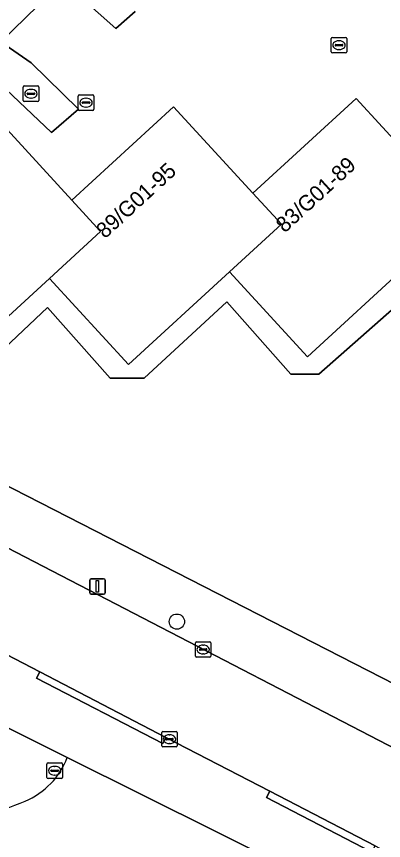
# Model space of a CAD drawing. Extents: x 160349 to 161355, y 381727 to 382854.
# Drawn here: x 160831.9 to 160855.5, y 381918.5 to 381971.4 of the extents above; entities that cross this region are included whole.
import ezdxf

# ---------------------------------------------------------------- set-up
doc = ezdxf.new("R2010")
doc.units = 0
for name, color, linetype in [('IMGEO_Boom', 7, 'Continuous'), ('IMGEO_Brandkraan', 7, 'Continuous'), ('IMGEO_Groenvoorziening', 7, 'Continuous'), ('IMGEO_Kolk', 7, 'Continuous'), ('IMGEO_Lichtmast', 7, 'Continuous'), ('IMGEO_Pand', 7, 'Continuous'), ('IMGEO_Pand_nummerreeks', 7, 'Continuous'), ('IMGEO_Rijbaan_lokaal_gesloten', 7, 'Continuous'), ('IMGEO_Rijbaan_lokaal_open', 7, 'Continuous'), ('IMGEO_Voetpad_halfverhard', 7, 'Continuous'), ('IMGEO_Voetpad_open', 7, 'Continuous')]:
    doc.layers.add(name, color=color, linetype=linetype)

msp = doc.modelspace()

# ---------------------------------------------------------------- linework, layer by layer
at = {"layer": 'IMGEO_Boom'}
msp.add_circle((160842.225, 381932.523), 0.489, dxfattribs=at)
at = {"layer": 'IMGEO_Brandkraan'}
for p, q in [((160832.359, 381965.97), (160832.359, 381966.822)), ((160832.434, 381966.896), (160833.286, 381966.896)), ((160832.618, 381966.39), (160832.618, 381966.402)), ((160832.661, 381966.439), (160833.059, 381966.439)), ((160832.847, 381966.676), (160832.872, 381966.676)), ((160833.102, 381966.402), (160833.102, 381966.39)), ((160833.36, 381966.822), (160833.36, 381965.97)), ((160833.286, 381965.896), (160832.434, 381965.896)), ((160833.056, 381966.353), (160832.658, 381966.353)), ((160832.87, 381966.116), (160832.845, 381966.116))]:
    msp.add_line(p, q, dxfattribs=at)
for points in [[(160832.359, 381965.97), (160832.359, 381966.822)], [(160832.434, 381966.896), (160833.286, 381966.896)], [(160833.36, 381966.822), (160833.36, 381965.97)], [(160833.286, 381965.896), (160832.434, 381965.896)]]:
    msp.add_lwpolyline(points, dxfattribs=at)
for centre, radius, start, end in [((160832.436, 381966.82), 0.0765, 91.552, 178.448), ((160832.436, 381966.82), 0.0765, 91.552, 178.448), ((160832.658, 381966.399), 0.0403, 85.8775, 175.7526), ((160832.655, 381966.389), 0.0366, 178.938, 274.7102), ((160833.059, 381966.396), 0.043, 264.8664, 352.4533), ((160833.063, 381966.401), 0.0386, 1.7309, 96.639), ((160833.284, 381966.82), 0.0765, 1.552, 88.448), ((160833.284, 381966.82), 0.0765, 1.552, 88.448), ((160832.436, 381965.972), 0.0765, 181.552, 268.448), ((160832.436, 381965.972), 0.0765, 181.552, 268.448), ((160833.284, 381965.972), 0.0765, 271.552, 358.448), ((160833.284, 381965.972), 0.0765, 271.552, 358.448)]:
    msp.add_arc(centre, radius, start, end, dxfattribs=at)
for centre, major_axis, ratio, start_param, end_param in [((160832.846, 381966.396), (-0.387, 0.002), 0.722429, 4.712389, 7.853982), ((160832.871, 381966.396), (-0.39, 0.002), 0.717154, 1.570796, 4.712389)]:
    msp.add_ellipse(centre, major_axis=major_axis, ratio=ratio, start_param=start_param, end_param=end_param, dxfattribs=at)
at = {"layer": 'IMGEO_Groenvoorziening'}
for points in [[(160846.705, 382000), (160826.232, 381970.197), (160830.848, 381967.059), (160834.186, 381963.909), (160835.921, 381965.403), (160832.878, 381968.382), (160830.935, 381969.72), (160834.915, 381973.622), (160838.299, 381970.579), (160839.544, 381971.672)], [(160857.092, 381953.481), (160851.346, 381948.396), (160849.539, 381948.396), (160845.436, 381953.033), (160840.118, 381948.151), (160837.948, 381948.151), (160833.93, 381952.676), (160828.424, 381947.509), (160826.348, 381947.553), (160820.135, 381954.319), (160820.858, 381954.984), (160824.089, 381957.951), (160823.753, 381958.316), (160823.374, 381957.967), (160823.024, 381958.349), (160823.707, 381958.976), (160820.18, 381961.222), (160815.016, 381954.084)], [(160815.913, 381949.125), (160859.732, 381926.696)]]:
    msp.add_lwpolyline(points, dxfattribs=at)
at = {"layer": 'IMGEO_Kolk'}
for p, q in [((160852.129, 381969.086), (160852.129, 381969.938)), ((160852.204, 381970.012), (160853.056, 381970.012)), ((160852.617, 381969.792), (160852.642, 381969.792)), ((160853.13, 381969.938), (160853.13, 381969.086)), ((160852.388, 381969.506), (160852.388, 381969.518)), ((160852.826, 381969.469), (160852.428, 381969.469)), ((160852.431, 381969.555), (160852.829, 381969.555)), ((160852.64, 381969.232), (160852.615, 381969.232)), ((160852.872, 381969.518), (160852.872, 381969.506)), ((160853.056, 381969.012), (160852.204, 381969.012)), ((160835.895, 381965.398), (160835.895, 381966.25)), ((160835.97, 381966.324), (160836.822, 381966.324)), ((160836.197, 381965.867), (160836.595, 381965.867)), ((160836.383, 381966.104), (160836.408, 381966.104)), ((160836.896, 381966.25), (160836.896, 381965.398)), ((160836.154, 381965.818), (160836.154, 381965.83)), ((160836.592, 381965.781), (160836.194, 381965.781)), ((160836.406, 381965.544), (160836.381, 381965.544)), ((160836.638, 381965.83), (160836.638, 381965.818)), ((160836.822, 381965.324), (160835.97, 381965.324)), ((160843.413, 381930.308), (160843.413, 381931.16)), ((160843.488, 381931.234), (160844.34, 381931.234)), ((160843.901, 381931.014), (160843.926, 381931.014)), ((160844.414, 381931.16), (160844.414, 381930.308)), ((160843.672, 381930.728), (160843.672, 381930.74)), ((160844.11, 381930.691), (160843.712, 381930.691)), ((160843.715, 381930.777), (160844.113, 381930.777)), ((160843.924, 381930.454), (160843.899, 381930.454)), ((160844.156, 381930.74), (160844.156, 381930.728)), ((160844.34, 381930.234), (160843.488, 381930.234)), ((160841.251, 381924.555), (160841.251, 381925.407)), ((160841.326, 381925.481), (160842.178, 381925.481)), ((160841.739, 381925.261), (160841.764, 381925.261)), ((160842.252, 381925.407), (160842.252, 381924.555)), ((160841.51, 381924.975), (160841.51, 381924.987)), ((160841.948, 381924.938), (160841.55, 381924.938)), ((160841.553, 381925.024), (160841.951, 381925.024)), ((160841.762, 381924.701), (160841.737, 381924.701)), ((160841.994, 381924.987), (160841.994, 381924.975)), ((160842.178, 381924.481), (160841.326, 381924.481)), ((160833.885, 381922.533), (160833.885, 381923.385)), ((160833.96, 381923.459), (160834.812, 381923.459)), ((160834.373, 381923.239), (160834.398, 381923.239)), ((160834.886, 381923.385), (160834.886, 381922.533)), ((160834.144, 381922.953), (160834.144, 381922.965)), ((160834.582, 381922.916), (160834.184, 381922.916)), ((160834.187, 381923.002), (160834.585, 381923.002)), ((160834.396, 381922.679), (160834.371, 381922.679)), ((160834.628, 381922.965), (160834.628, 381922.953)), ((160834.812, 381922.459), (160833.96, 381922.459))]:
    msp.add_line(p, q, dxfattribs=at)
for points in [[(160852.129, 381969.086), (160852.129, 381969.938)], [(160852.204, 381970.012), (160853.056, 381970.012)], [(160853.13, 381969.938), (160853.13, 381969.086)], [(160853.056, 381969.012), (160852.204, 381969.012)], [(160835.895, 381965.398), (160835.895, 381966.25)], [(160835.97, 381966.324), (160836.822, 381966.324)], [(160836.896, 381966.25), (160836.896, 381965.398)], [(160836.822, 381965.324), (160835.97, 381965.324)], [(160843.413, 381930.308), (160843.413, 381931.16)], [(160843.488, 381931.234), (160844.34, 381931.234)], [(160844.414, 381931.16), (160844.414, 381930.308)], [(160844.34, 381930.234), (160843.488, 381930.234)], [(160841.251, 381924.555), (160841.251, 381925.407)], [(160841.326, 381925.481), (160842.178, 381925.481)], [(160842.252, 381925.407), (160842.252, 381924.555)], [(160842.178, 381924.481), (160841.326, 381924.481)], [(160833.885, 381922.533), (160833.885, 381923.385)], [(160833.96, 381923.459), (160834.812, 381923.459)], [(160834.886, 381923.385), (160834.886, 381922.533)], [(160834.812, 381922.459), (160833.96, 381922.459)]]:
    msp.add_lwpolyline(points, dxfattribs=at)
for centre, radius, start, end in [((160852.206, 381969.936), 0.0765, 91.552, 178.448), ((160852.206, 381969.936), 0.0765, 91.552, 178.448), ((160853.054, 381969.936), 0.0765, 1.552, 88.448), ((160853.054, 381969.936), 0.0765, 1.552, 88.448), ((160852.206, 381969.088), 0.0765, 181.552, 268.448), ((160852.206, 381969.088), 0.0765, 181.552, 268.448), ((160852.428, 381969.515), 0.0403, 85.8775, 175.7526), ((160852.425, 381969.505), 0.0366, 178.938, 274.7102), ((160852.829, 381969.512), 0.043, 264.8664, 352.4533), ((160852.833, 381969.517), 0.0386, 1.7309, 96.639), ((160853.054, 381969.088), 0.0765, 271.552, 358.448), ((160853.054, 381969.088), 0.0765, 271.552, 358.448), ((160835.972, 381966.248), 0.0765, 91.552, 178.448), ((160835.972, 381966.248), 0.0765, 91.552, 178.448), ((160836.194, 381965.827), 0.0403, 85.8775, 175.7526), ((160836.599, 381965.829), 0.0386, 1.7309, 96.639), ((160836.82, 381966.248), 0.0765, 1.552, 88.448), ((160836.82, 381966.248), 0.0765, 1.552, 88.448), ((160835.972, 381965.4), 0.0765, 181.552, 268.448), ((160835.972, 381965.4), 0.0765, 181.552, 268.448), ((160836.191, 381965.817), 0.0366, 178.938, 274.7102), ((160836.595, 381965.824), 0.043, 264.8664, 352.4533), ((160836.82, 381965.4), 0.0765, 271.552, 358.448), ((160836.82, 381965.4), 0.0765, 271.552, 358.448), ((160843.49, 381931.158), 0.0765, 91.552, 178.448), ((160843.49, 381931.158), 0.0765, 91.552, 178.448), ((160844.338, 381931.158), 0.0765, 1.552, 88.448), ((160844.338, 381931.158), 0.0765, 1.552, 88.448), ((160843.712, 381930.737), 0.0403, 85.8775, 175.7526), ((160843.709, 381930.727), 0.0366, 178.938, 274.7102), ((160844.113, 381930.734), 0.043, 264.8664, 352.4533), ((160844.117, 381930.739), 0.0386, 1.7309, 96.639), ((160843.49, 381930.31), 0.0765, 181.552, 268.448), ((160843.49, 381930.31), 0.0765, 181.552, 268.448), ((160844.338, 381930.31), 0.0765, 271.552, 358.448), ((160844.338, 381930.31), 0.0765, 271.552, 358.448), ((160841.328, 381925.405), 0.0765, 91.552, 178.448), ((160841.328, 381925.405), 0.0765, 91.552, 178.448), ((160842.176, 381925.405), 0.0765, 1.552, 88.448), ((160842.176, 381925.405), 0.0765, 1.552, 88.448), ((160841.55, 381924.984), 0.0403, 85.8775, 175.7526), ((160841.547, 381924.974), 0.0366, 178.938, 274.7102), ((160841.951, 381924.981), 0.043, 264.8664, 352.4533), ((160841.955, 381924.986), 0.0386, 1.7309, 96.639), ((160841.328, 381924.557), 0.0765, 181.552, 268.448), ((160841.328, 381924.557), 0.0765, 181.552, 268.448), ((160842.176, 381924.557), 0.0765, 271.552, 358.448), ((160842.176, 381924.557), 0.0765, 271.552, 358.448), ((160833.962, 381923.383), 0.0765, 91.552, 178.448), ((160833.962, 381923.383), 0.0765, 91.552, 178.448), ((160834.81, 381923.383), 0.0765, 1.552, 88.448), ((160834.81, 381923.383), 0.0765, 1.552, 88.448), ((160833.962, 381922.535), 0.0765, 181.552, 268.448), ((160833.962, 381922.535), 0.0765, 181.552, 268.448), ((160834.184, 381922.962), 0.0403, 85.8775, 175.7526), ((160834.181, 381922.952), 0.0366, 178.938, 274.7102), ((160834.585, 381922.959), 0.043, 264.8664, 352.4533), ((160834.589, 381922.964), 0.0386, 1.7309, 96.639), ((160834.81, 381922.535), 0.0765, 271.552, 358.448), ((160834.81, 381922.535), 0.0765, 271.552, 358.448)]:
    msp.add_arc(centre, radius, start, end, dxfattribs=at)
for centre, major_axis, ratio, start_param, end_param in [((160852.616, 381969.512), (-0.387, 0.002), 0.722429, 4.712389, 7.853982), ((160852.641, 381969.512), (-0.39, 0.002), 0.717154, 1.570796, 4.712389), ((160836.382, 381965.824), (-0.387, 0.002), 0.722429, 4.712389, 7.853982), ((160836.407, 381965.824), (-0.39, 0.002), 0.717154, 1.570796, 4.712389), ((160843.9, 381930.734), (-0.387, 0.002), 0.722429, 4.712389, 7.853982), ((160843.925, 381930.734), (-0.39, 0.002), 0.717154, 1.570796, 4.712389), ((160841.738, 381924.981), (-0.387, 0.002), 0.722429, 4.712389, 7.853982), ((160841.763, 381924.981), (-0.39, 0.002), 0.717154, 1.570796, 4.712389), ((160834.372, 381922.959), (-0.387, 0.002), 0.722429, 4.712389, 7.853982), ((160834.397, 381922.959), (-0.39, 0.002), 0.717154, 1.570796, 4.712389)]:
    msp.add_ellipse(centre, major_axis=major_axis, ratio=ratio, start_param=start_param, end_param=end_param, dxfattribs=at)
at = {"layer": 'IMGEO_Lichtmast'}
for p, q in [((160836.734, 381935.28), (160837.524, 381935.28)), ((160837.524, 381935.28), (160836.734, 381935.28)), ((160836.634, 381934.38), (160836.634, 381935.18)), ((160836.634, 381935.18), (160836.634, 381934.38)), ((160837.624, 381935.18), (160837.624, 381934.38)), ((160837.624, 381934.38), (160837.624, 381935.18)), ((160837.524, 381934.28), (160836.734, 381934.28)), ((160836.734, 381934.28), (160837.524, 381934.28))]:
    msp.add_line(p, q, dxfattribs=at)
msp.add_lwpolyline([(160837.054, 381935.155), (160837.204, 381935.155), (160837.204, 381934.405), (160837.054, 381934.405), (160837.054, 381935.155)], dxfattribs=at)
for centre, start, end in [((160836.734, 381935.18), 90, 180), ((160836.734, 381935.18), 90, 180), ((160837.524, 381935.18), 0, 90), ((160837.524, 381935.18), 360, 90), ((160836.734, 381934.38), 180, 270), ((160836.734, 381934.38), 180, 270), ((160837.524, 381934.38), 270, 0), ((160837.524, 381934.38), 270, 0)]:
    msp.add_arc(centre, 0.1, start, end, dxfattribs=at)
at = {"layer": 'IMGEO_Pand'}
for points in [[(160847.108, 381960.01), (160848.929, 381958.026), (160845.599, 381954.97), (160850.598, 381949.525), (160857.211, 381955.595), (160860.556, 381958.665), (160858.81, 381960.567), (160853.736, 381966.095)], [(160847.108, 381960.01), (160842.019, 381965.554), (160835.488, 381959.558), (160837.325, 381957.557), (160834.045, 381954.546), (160839.118, 381949.02), (160845.599, 381954.97), (160848.929, 381958.026)], [(160837.325, 381957.557), (160835.488, 381959.558), (160830.39, 381965.111), (160823.707, 381958.976), (160823.024, 381958.349), (160823.374, 381957.967), (160823.753, 381958.316), (160824.089, 381957.951), (160825.013, 381956.944), (160822.124, 381954.291), (160827.449, 381948.491), (160834.045, 381954.546)]]:
    msp.add_lwpolyline(points, close=True, dxfattribs=at)
at = {"layer": 'IMGEO_Rijbaan_lokaal_gesloten'}
msp.add_lwpolyline([(160835.192, 381923.816), (160831.29, 381925.762), (160830.732, 381924.65)], dxfattribs=at)
for centre, radius, start, end in [((160830.605, 381925.532), 4.898, 292.5894, 339.4893), ((160825.735, 381936.84), 17.21, 274.2167, 293.0977)]:
    msp.add_arc(centre, radius, start, end, dxfattribs=at)
at = {"layer": 'IMGEO_Rijbaan_lokaal_open'}
msp.add_lwpolyline([(160783.615, 381955.602), (160786.617, 381954.029), (160791.949, 381951.067), (160794.272, 381949.777), (160824.977, 381933.582), (160825.379, 381933.478), (160833.426, 381929.292), (160841.525, 381925.098), (160848.187, 381921.638), (160854.945, 381918.142), (160855.781, 381917.696), (160857.744, 381916.681), (160860.432, 381922.204), (160858.668, 381923.098), (160813.262, 381946.618), (160812.854, 381946.829), (160799.884, 381953.571), (160798.792, 381954.127), (160785.618, 381960.974)], dxfattribs=at)
at = {"layer": 'IMGEO_Voetpad_halfverhard'}
msp.add_lwpolyline([(160857.211, 381955.595), (160850.598, 381949.525), (160845.599, 381954.97), (160839.118, 381949.02), (160834.045, 381954.546), (160827.449, 381948.491), (160822.124, 381954.291), (160825.013, 381956.944), (160824.089, 381957.951), (160820.858, 381954.984), (160820.135, 381954.319), (160826.348, 381947.553), (160828.424, 381947.509), (160833.93, 381952.676), (160837.948, 381948.151), (160840.118, 381948.151), (160845.436, 381953.033), (160849.539, 381948.396), (160851.346, 381948.396), (160857.092, 381953.481)], dxfattribs=at)
at = {"layer": 'IMGEO_Voetpad_open'}
for points in [[(160839.544, 381971.672), (160838.299, 381970.579), (160834.915, 381973.622), (160830.935, 381969.72), (160832.878, 381968.382), (160835.921, 381965.403), (160834.186, 381963.909), (160830.848, 381967.059), (160826.232, 381970.197), (160825.506, 381968.975), (160829.211, 381966.295), (160823.689, 381960.942), (160821.136, 381962.535), (160820.18, 381961.222), (160823.707, 381958.976), (160830.39, 381965.111), (160835.488, 381959.558), (160842.019, 381965.554), (160847.108, 381960.01), (160853.736, 381966.095), (160858.81, 381960.567)], [(160740.787, 381973.103), (160745.256, 381970.771), (160785.29, 381949.403), (160785.583, 381949.242), (160789.391, 381947.15), (160789.629, 381947.019), (160831.29, 381925.762), (160835.192, 381923.816), (160854.514, 381914.18), (160854.739, 381917.742), (160847.981, 381921.238), (160848.187, 381921.638), (160841.525, 381925.098), (160841.319, 381924.698), (160833.22, 381928.892), (160833.426, 381929.292), (160825.379, 381933.478), (160824.977, 381933.582), (160824.596, 381933.592), (160822.597, 381933.17)], [(160812.854, 381946.829), (160813.262, 381946.618), (160858.668, 381923.098), (160859.732, 381926.696), (160815.913, 381949.125)], [(160793.675, 381914.77), (160798.607, 381909.202), (160805.397, 381915.215), (160810.299, 381909.679), (160817.101, 381915.703), (160822.045, 381910.121), (160828.833, 381916.132), (160833.696, 381910.641), (160840.55, 381916.712), (160847.359, 381909.025), (160848.175, 381908.11), (160848.899, 381907.299), (160854.514, 381914.18), (160835.192, 381923.816)]]:
    msp.add_lwpolyline(points, dxfattribs=at)
for points in [[(160833.426, 381929.292), (160833.22, 381928.892), (160841.319, 381924.698), (160841.525, 381925.098)], [(160854.945, 381918.142), (160848.187, 381921.638), (160847.981, 381921.238), (160854.739, 381917.742)]]:
    msp.add_lwpolyline(points, close=True, dxfattribs=at)
for centre, radius, start, end in [((160830.605, 381925.532), 4.898, 292.5894, 339.4893), ((160825.735, 381936.84), 17.21, 274.2167, 293.0977)]:
    msp.add_arc(centre, radius, start, end, dxfattribs=at)

# ---------------------------------------------------------------- texts
at = {"layer": 'IMGEO_Pand_nummerreeks'}
for s, rotation, p in [('83/G01-89', 42.5543, (160849.142, 381957.425)), ('89/G01-95', 42.5545, (160837.61, 381957.054))]:
    msp.add_text(s, height=1, rotation=rotation, dxfattribs=at).set_placement(p)

doc.saveas('drawing.dxf')
